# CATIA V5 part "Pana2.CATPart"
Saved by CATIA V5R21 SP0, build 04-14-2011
Part number: Pana2
Bounding box of the stored display mesh (mm): x -0.9 to 0.9, y 1 to 4, z 41.1 to 47.9
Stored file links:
  C:\Users\MIRCEA\Desktop\PRRO\CATIAV5\Pana2.CATPart
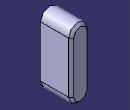
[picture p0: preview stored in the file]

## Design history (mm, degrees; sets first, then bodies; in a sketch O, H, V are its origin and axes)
Body1 (main body)
  Plane1: type Offset, RefPlane zx-plane, Offset 4
  Sketch1 on Plane1, origin (0, 4, 0), H (-1, 0, 0), V (0, 0, 1)
    construction line L1 (0, 42) -> (0, 47)
    line L2 (-0.9, 42) -> (-0.9, 47)
    line L3 (0.9, 47) -> (0.9, 42)
    arc A1 centre (0, 47) radius 0.9 from (-0.9, 47) to (0.9, 47) cw
    arc A2 centre (0, 42) radius 0.9 from (0.9, 42) to (-0.9, 42) cw
    length L1 = 5
    distance L1 L2 = 0.9
    vertical: L1 V
    tangency: A1 L2, A2 L2, A1 L3, A2 L3
  Pad1: profile Sketch1, direction (0, -1, 0), length 3
  Chamfer1: length 0.25, angle 45, on edge [face of Pad1 from Sketch1.A2 | start face of Pad1]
